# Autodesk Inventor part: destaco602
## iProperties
Title: destaco602
Author: GJOHNST2
Shininess: 20.0
Length Units: 11272
Angle Units: 11286
Time Units: 11279
Mass Units: 11290
Length Display Precision: 3
Angle Display Precision: 2
Compacted: True
PropertySet Name: _Private Model Information
Created: 2001-11
Part Number: shaft
Material: Bronze, Soft Tin
Document SubType Name: Modeling
Designer: GJOHNST2
Control State: 0
Master: False
Checked Out: False
PropertySet Name: Design Tracking Control
Density: 8.874
Volumn: 3.024848126773105
Area: 21.09480506663282
PropertySet Name: Model Information
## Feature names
1. Extrusion1
2. Hole1
3. Chamfer1
4. Extrusion2
